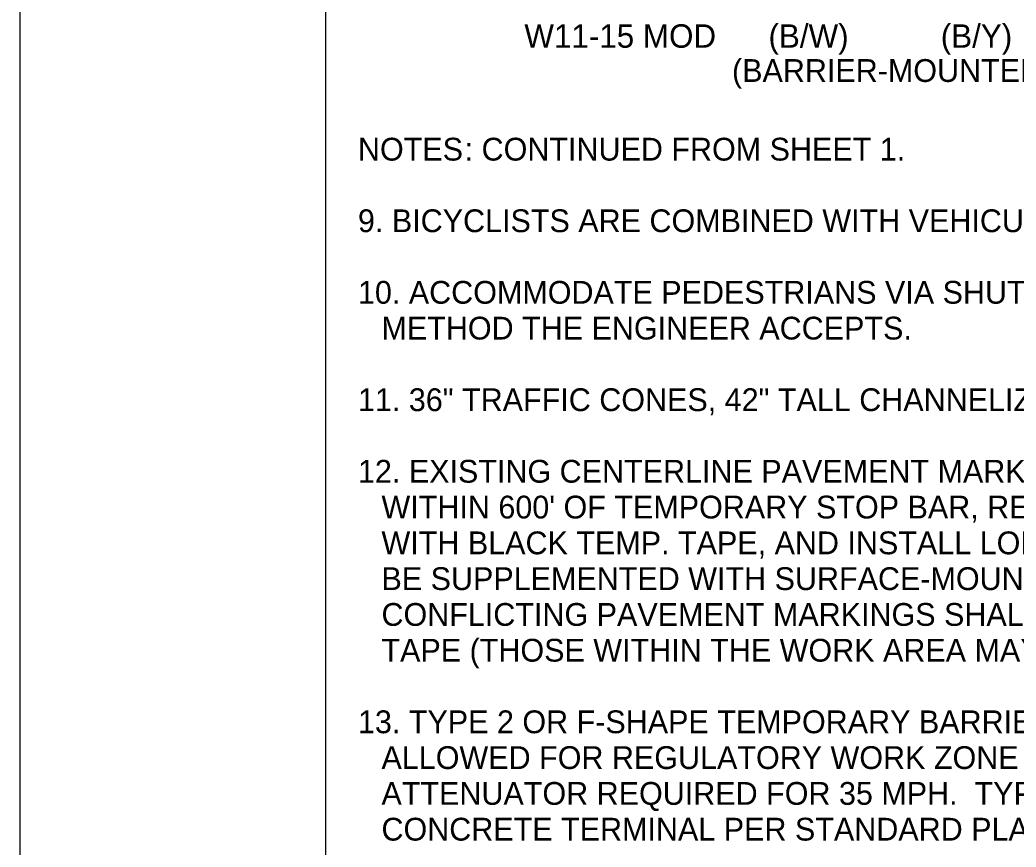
# Model space of a CAD drawing. Extents: x 99976 to 100136, y 99905 to 100011.
# Drawn here: x 100019.062 to 100022.12, y 99942.89 to 99945.43 of the extents above; entities that cross this region are included whole.
import ezdxf

# ---------------------------------------------------------------- set-up
doc = ezdxf.new("R2010")
doc.units = 0
for name, color, linetype in [('SH_GI_GeneralNotesBodyText', 7, 'Continuous'), ('SH_GI_PlotLimits', 7, 'Continuous'), ('SH_GI_SheetBorder', 7, 'Continuous'), ('TR_SN_ConstructionSigns', 7, 'Continuous'), ('TR_WZ_WorkZoneDetails', 7, 'Continuous')]:
    doc.layers.add(name, color=color, linetype=linetype)

msp = doc.modelspace()

# ---------------------------------------------------------------- linework, layer by layer
at = {"layer": 'SH_GI_PlotLimits'}
msp.add_lwpolyline([(100019.0625, 99939.6875), (100036.0625, 99939.6875), (100036.0625, 99950.6875), (100019.0625, 99950.6875)], close=True, dxfattribs=at)
at = {"layer": 'SH_GI_SheetBorder'}
msp.add_line((100020, 99950.375), (100020, 99940), dxfattribs=at)

# ---------------------------------------------------------------- texts
at = {"layer": 'SH_GI_GeneralNotesBodyText'}
for s, p in [('NOTES', (100020.1, 99944.9978)), (': CONTINUED FROM SHEET 1.', (100020.4275, 99944.9978)), ('9. BICYCLISTS ARE COMBINED WITH VEHICULAR TRAFFIC THROUGH THE LANE CLOSURE.', (100020.1, 99944.778)), ('10. ACCOMMODATE PEDESTRIANS VIA SHUTTLE THROUGH LANE CLOSURE OR ANOTHER ', (100020.1, 99944.5582)), ('METHOD THE ENGINEER ACCEPTS.', (100020.1722, 99944.4483)), ('11. 36" TRAFFIC CONES, 42" TALL CHANNELIZATION DEVICES, OR TRAFFIC SAFETY DRUMS OK.', (100020.1, 99944.2285)), ('12. EXISTING CENTERLINE PAVEMENT MARKINGS MAY VARY. IF PASSING ZONE PRESENT ', (100020.1, 99944.0087)), ("WITHIN 600' OF TEMPORARY STOP BAR, REMOVE EXISTING CENTERLINE MARKING, OR COVER ", (100020.1722, 99943.8988)), ('WITH BLACK TEMP. TAPE, AND INSTALL LONG-DURATION TEMP. DOUBLE YELLOW LINE (MAY ', (100020.1722, 99943.7889)), ("BE SUPPLEMENTED WITH SURFACE-MOUNTED TYPE 2YY RPMs @ 40' SPACING).  ALL OTHER ", (100020.1722, 99943.679)), ('CONFLICTING PAVEMENT MARKINGS SHALL BE REMOVED OR COVERED WITH BLACK TEMP. ', (100020.1722, 99943.5691)), ('TAPE (THOSE WITHIN THE WORK AREA MAY REMAIN AS SHOWN).', (100020.1722, 99943.4592)), ('13. TYPE 2 OR F-SHAPE TEMPORARY BARRIER PERMITTED.  SLOPED CONCRETE TERMINAL ', (100020.1, 99943.2394)), ('ALLOWED FOR REGULATORY WORK ZONE SPEED LIMITS 25 MPH OR LESS BUT TL-2 IMPACT ', (100020.1722, 99943.1295)), ('ATTENUATOR REQUIRED FOR 35 MPH.  TYPE 2 TEMPORARY BARRIER AND SLOPED ', (100020.1722, 99943.0196)), ('CONCRETE TERMINAL PER STANDARD PLAN K.80-32 BUT CONTRACTOR SHALL SELECT ', (100020.1722, 99942.9097))]:
    msp.add_text(s, height=0.07, rotation=360, dxfattribs=at).set_placement(p)
at = {"layer": 'TR_SN_ConstructionSigns'}
for s, p in [('W11-15 MOD', (100020.6107, 99945.3443)), ('(B/W)', (100021.36, 99945.3443)), ('(B/Y)', (100021.8888, 99945.3443))]:
    msp.add_text(s, height=0.072, rotation=360, dxfattribs=at).set_placement(p)
at = {"layer": 'TR_WZ_WorkZoneDetails'}
msp.add_text('(BARRIER-MOUNTED)', height=0.07, dxfattribs=at).set_placement((100021.2481, 99945.2393))

doc.saveas('drawing.dxf')
